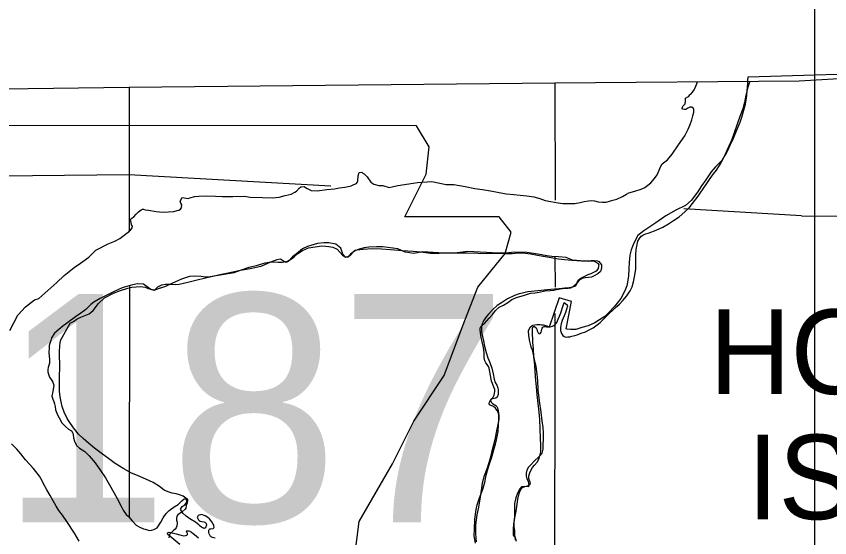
# Model space of a CAD drawing. Extents: x 77230 to 630905, y 790554 to 1662844.
# Drawn here: x 357646 to 367817, y 1633900 to 1640415 of the extents above; entities that cross this region are included whole.
import ezdxf

# ---------------------------------------------------------------- set-up
doc = ezdxf.new("R2010")
doc.units = 0
for name, color, linetype in [('Level 12', 7, 'Continuous'), ('Level 14', 7, 'Continuous'), ('Level 16', 7, 'Continuous'), ('Level 17', 7, 'Continuous'), ('Level 24', 7, 'Continuous'), ('Level 27', 7, 'Continuous'), ('Level 28', 7, 'Continuous')]:
    doc.layers.add(name, color=color, linetype=linetype)

msp = doc.modelspace()

# ---------------------------------------------------------------- linework, layer by layer
at = {"layer": 'Level 12'}
for points in [[(366796, 1639660), (368744, 1639716)], [(364322, 1636536), (364349, 1636542), (364368, 1636551), (364383, 1636563), (364393, 1636574), (364405, 1636591), (364422, 1636630), (364438, 1636668), (364454, 1636708), (364462, 1636734), (364475, 1636777), (364497, 1636841), (364534, 1636809), (364537, 1636790), (364536, 1636785), (364531, 1636768), (364522, 1636738), (364513, 1636712), (364498, 1636674), (364472, 1636613), (364460, 1636572), (364457, 1636557), (364453, 1636517), (364453, 1636491), (364463, 1636453), (364481, 1636425), (364498, 1636413), (364520, 1636406), (364542, 1636408), (364566, 1636412), (364594, 1636417), (364629, 1636427), (364659, 1636437), (364711, 1636456), (364763, 1636474), (364819, 1636501), (364861, 1636524), (364911, 1636559), (364949, 1636590), (364980, 1636621), (365017, 1636661), (365058, 1636700), (365104, 1636744), (365155, 1636791), (365189, 1636820), (365232, 1636865), (365280, 1636924), (365320, 1636983), (365347, 1637035), (365365, 1637098), (365381, 1637180), (365391, 1637259), (365393, 1637360), (365393, 1637430), (365398, 1637502), (365405, 1637544), (365420, 1637605), (365438, 1637639), (365459, 1637668), (365479, 1637681), (365507, 1637692), (365558, 1637709), (365648, 1637743), (365730, 1637781), (365802, 1637822), (365865, 1637863), (365934, 1637909), (366006, 1637970), (366059, 1638023), (366103, 1638075), (366172, 1638169), (366197, 1638205), (366281, 1638326), (366324, 1638388), (366365, 1638447), (366403, 1638494), (366439, 1638550), (366467, 1638601), (366499, 1638658), (366521, 1638696), (366543, 1638739), (366573, 1638805), (366613, 1638891), (366651, 1638982), (366697, 1639093), (366719, 1639154), (366763, 1639315), (366773, 1639368), (366779, 1639426), (366787, 1639491), (366789, 1639523), (366790, 1639535), (366793, 1639577), (366794, 1639611), (366796, 1639660)], [(359928, 1634063), (359886, 1634093), (359815, 1634136), (359772, 1634168), (359729, 1634206), (359701, 1634259), (359722, 1634289), (359733, 1634298), (359753, 1634312), (359769, 1634332), (359778, 1634352), (359776, 1634370), (359765, 1634394), (359734, 1634419), (359688, 1634438), (359645, 1634449), (359595, 1634458), (359543, 1634474), (359496, 1634496), (359437, 1634540), (359357, 1634590), (359264, 1634631), (359162, 1634677), (359087, 1634707), (358989, 1634761), (358883, 1634828), (358798, 1634890), (358723, 1634943), (358624, 1635018), (358550, 1635081), (358482, 1635141), (358424, 1635193), (358361, 1635274), (358308, 1635352), (358282, 1635391), (358245, 1635470), (358220, 1635541), (358206, 1635600), (358193, 1635661), (358188, 1635733), (358185, 1635811), (358185, 1635870), (358186, 1635935), (358191, 1636011), (358192, 1636090), (358188, 1636152), (358185, 1636222), (358189, 1636297), (358199, 1636363), (358321, 1636579), (358362, 1636601), (358409, 1636633), (358454, 1636655), (358557, 1636699), (358607, 1636739), (358673, 1636827), (358747, 1636897), (358863, 1636955), (358948, 1636990), (359039, 1637019), (359092, 1637030), (359147, 1637036), (359199, 1637040), (359258, 1637029), (359293, 1637012), (359368, 1636996), (359384, 1637001), (359398, 1637017), (359414, 1637035), (359465, 1637058), (359510, 1637066), (359561, 1637068), (359636, 1637064), (359682, 1637068), (359792, 1637092), (359893, 1637119), (360027, 1637153), (360122, 1637174), (360294, 1637202), (360372, 1637215), (360464, 1637247), (360557, 1637279), (360662, 1637307), (360758, 1637336), (360835, 1637346), (360921, 1637344), (360975, 1637341), (361039, 1637356), (361086, 1637383), (361125, 1637413), (361167, 1637451), (361223, 1637489), (361298, 1637523), (361465, 1637547), (361515, 1637543)], [(361515, 1637543), (361555, 1637539), (361606, 1637530), (361658, 1637506), (361723, 1637429), (361748, 1637413), (361780, 1637408)], [(361780, 1637408), (361802, 1637418), (361819, 1637434), (361837, 1637456), (361861, 1637477), (361885, 1637493), (361904, 1637499), (361978, 1637507), (362100, 1637513), (362212, 1637508), (362324, 1637500), (362477, 1637490), (362609, 1637479), (362700, 1637470), (362827, 1637457), (362934, 1637455), (363019, 1637458), (363105, 1637459), (363181, 1637459), (363283, 1637458), (363422, 1637455), (363530, 1637453), (363656, 1637455), (363761, 1637451), (363845, 1637451), (363922, 1637458), (363974, 1637458), (364074, 1637448), (364162, 1637431), (364209, 1637421), (364309, 1637405), (364426, 1637385), (364500, 1637377), (364591, 1637369), (364714, 1637360), (364791, 1637360), (364836, 1637362), (364878, 1637364), (364913, 1637360), (364929, 1637352), (364963, 1637311), (364965, 1637268), (364950, 1637226), (364916, 1637196), (364871, 1637171), (364838, 1637156), (364800, 1637151), (364759, 1637148), (364720, 1637138), (364679, 1637112), (364645, 1637068), (364612, 1637039), (364578, 1637020), (364545, 1637012), (364478, 1637010), (364436, 1637011), (364376, 1637007), (364283, 1636998), (364208, 1636990), (364041, 1636972), (363974, 1636955), (363935, 1636946), (363875, 1636925), (363790, 1636883), (363714, 1636836), (363658, 1636800), (363603, 1636753), (363551, 1636692), (363523, 1636658), (363490, 1636612), (363469, 1636559), (363464, 1636531), (363462, 1636502), (363463, 1636473), (363475, 1636416), (363487, 1636358), (363500, 1636292), (363520, 1636213), (363544, 1636147), (363566, 1636089), (363593, 1636018), (363607, 1635949), (363620, 1635882), (363635, 1635839), (363654, 1635805), (363667, 1635772), (363673, 1635746), (363670, 1635689), (363658, 1635656), (363642, 1635645), (363621, 1635639), (363601, 1635634), (363590, 1635632), (363576, 1635618), (363585, 1635593)], [(363890, 1633873), (363882, 1633906), (363875, 1633917), (363865, 1633931), (363862, 1633947), (363862, 1634006), (363868, 1634070), (363881, 1634147), (363895, 1634230), (363908, 1634318), (363917, 1634381), (363933, 1634454), (363945, 1634486), (363962, 1634515), (363977, 1634529), (364003, 1634540), (364024, 1634546), (364049, 1634554), (364055, 1634562), (364076, 1634578), (364073, 1634597), (364065, 1634617), (364059, 1634629), (364056, 1634639), (364056, 1634674), (364071, 1634725), (364102, 1634777), (364126, 1634808), (364158, 1634845), (364186, 1634891), (364207, 1634975), (364207, 1635058), (364201, 1635142), (364196, 1635261), (364191, 1635379), (364184, 1635470), (364173, 1635577), (364159, 1635687), (364149, 1635789), (364142, 1635865), (364133, 1635979), (364129, 1636058), (364119, 1636164), (364115, 1636256), (364105, 1636342), (364099, 1636481), (364102, 1636511), (364107, 1636531), (364112, 1636539), (364125, 1636539), (364145, 1636524), (364153, 1636507), (364159, 1636485), (364171, 1636461), (364181, 1636450), (364189, 1636448), (364196, 1636450), (364202, 1636456), (364208, 1636468), (364212, 1636485), (364216, 1636506), (364222, 1636520)], [(364222, 1636520), (364229, 1636530), (364245, 1636538), (364257, 1636538), (364277, 1636537), (364300, 1636535), (364322, 1636536)], [(363585, 1635593), (363596, 1635582), (363614, 1635570), (363631, 1635560), (363647, 1635548), (363654, 1635541), (363663, 1635523)], [(363663, 1635523), (363671, 1635485), (363678, 1635429), (363678, 1635382), (363672, 1635336), (363648, 1635213), (363629, 1635125), (363608, 1635042), (363590, 1634965), (363568, 1634877), (363533, 1634770), (363497, 1634673), (363473, 1634583), (363462, 1634518), (363438, 1634358), (363425, 1634280), (363406, 1634185), (363390, 1634063), (363388, 1633950), (363396, 1633850)], [(360134, 1633893), (360099, 1633903), (360084, 1633913), (360072, 1633924), (360058, 1633947), (360052, 1633965), (360053, 1633993), (360058, 1634003), (360066, 1634010), (360077, 1634013), (360108, 1634016), (360116, 1634024), (360121, 1634031), (360118, 1634047), (360115, 1634055), (360107, 1634071), (360092, 1634097), (360079, 1634116), (360061, 1634135), (360052, 1634143), (360008, 1634175), (359962, 1634191), (359922, 1634177), (359915, 1634170), (359909, 1634152), (359914, 1634140), (359925, 1634124), (359934, 1634116), (359947, 1634108), (359968, 1634104), (359989, 1634100), (360005, 1634093), (360013, 1634085), (360019, 1634077), (360023, 1634059), (360020, 1634045), (360018, 1634035), (360008, 1634024), (360003, 1634020), (359998, 1634017)], [(359998, 1634017), (359992, 1634018), (359981, 1634021), (359977, 1634023), (359962, 1634034), (359947, 1634046), (359928, 1634063)], [(359689, 1633815), (359541, 1633940), (359535, 1633957), (359537, 1633961), (359559, 1633968), (359593, 1633963), (359612, 1633957), (359645, 1633949), (359689, 1633936), (359723, 1633928), (359742, 1633924), (359768, 1633926), (359778, 1633931), (359787, 1633942), (359787, 1633944), (359787, 1633951), (359783, 1633960), (359775, 1633980), (359775, 1633982), (359779, 1633985), (359793, 1633988), (359802, 1633987), (359814, 1633982), (359822, 1633978), (359835, 1633970), (359857, 1633955), (359873, 1633940), (359899, 1633919), (359924, 1633897)]]:
    msp.add_lwpolyline(points, dxfattribs=at)
at = {"layer": 'Level 14'}
for points in [[(367437, 1639610), (369554, 1639734), (374777, 1639819), (378981, 1639866)], [(338556, 1639267), (343823, 1639351), (349273, 1639417), (354630, 1639473), (359059, 1639529), (364378, 1639584), (367437, 1639610)]]:
    msp.add_lwpolyline(points, dxfattribs=at)
at = {"layer": 'Level 16'}
for points in [[(359059, 1639529), (359058, 1638419), (359056, 1637728)], [(364378, 1639584), (364383, 1638118)], [(361579, 1638291), (359054, 1638435), (354628, 1638390)], [(367464, 1637920), (365992, 1638009)], [(367464, 1637920), (369592, 1637905), (374779, 1637490), (379177, 1637619)], [(364378, 1637415), (364384, 1637031)], [(359063, 1637037), (359057, 1634152)], [(364382, 1636702), (364374, 1632814), (364326, 1631279)]]:
    msp.add_lwpolyline(points, dxfattribs=at)
at = {"layer": 'Level 17'}
for points in [[(363575, 1638234), (363663, 1638219), (363773, 1638196), (363867, 1638189), (363947, 1638180), (364028, 1638170), (364116, 1638159), (364194, 1638138), (364260, 1638113), (364332, 1638099), (364422, 1638084), (364482, 1638077), (364566, 1638076), (364632, 1638076), (364698, 1638089), (364748, 1638099), (364802, 1638110), (364836, 1638114), (364876, 1638109), (364924, 1638097), (364972, 1638094), (365022, 1638094), (365106, 1638117), (365154, 1638132), (365227, 1638164), (365275, 1638193), (365305, 1638209), (365379, 1638230), (365459, 1638257), (365506, 1638277), (365580, 1638336), (365625, 1638389), (365659, 1638433), (365686, 1638491), (365702, 1638533), (365724, 1638570), (365787, 1638622), (365848, 1638693), (365927, 1638810), (366006, 1638921), (366047, 1639003), (366073, 1639064), (366092, 1639122), (366106, 1639172), (366117, 1639218), (366119, 1639250), (366115, 1639264), (366095, 1639280), (366069, 1639278), (366045, 1639266), (366019, 1639250), (366001, 1639249), (365981, 1639253), (365973, 1639257), (365973, 1639269), (365975, 1639279), (365984, 1639295), (366008, 1639323), (366016, 1639358), (366016, 1639392), (366045, 1639408), (366055, 1639416), (366073, 1639436), (366079, 1639442), (366103, 1639465), (366121, 1639495), (366124, 1639497), (366132, 1639513), (366144, 1639543), (366160, 1639585), (366162, 1639594)], [(366818, 1639600), (366810, 1639580), (366792, 1639530), (366767, 1639429), (366750, 1639339), (366729, 1639259), (366692, 1639164), (366659, 1639066), (366624, 1638957), (366592, 1638877), (366579, 1638845), (366532, 1638736), (366500, 1638670), (366467, 1638615), (366388, 1638534), (366336, 1638470), (366267, 1638371), (366216, 1638296), (366165, 1638218), (366084, 1638113), (366012, 1638052), (365893, 1637991), (365766, 1637923), (365641, 1637834), (365545, 1637767), (365494, 1637736), (365418, 1637678), (365369, 1637581), (365334, 1637497), (365317, 1637432), (365311, 1637338), (365306, 1637262), (365303, 1637168), (365280, 1637047), (365257, 1636983), (365204, 1636890), (365158, 1636830), (365121, 1636784), (365060, 1636717), (365004, 1636664), (364940, 1636624), (364879, 1636583), (364795, 1636546), (364717, 1636525), (364642, 1636500), (364576, 1636502), (364536, 1636507), (364520, 1636511), (364588, 1636852), (364436, 1636897), (364311, 1636531), (364283, 1636545), (364239, 1636554), (364213, 1636556), (364195, 1636558), (364181, 1636560), (364153, 1636558), (364129, 1636557), (364101, 1636551), (364091, 1636545), (364066, 1636523), (364048, 1636485), (364052, 1636422), (364063, 1636352), (364082, 1636287), (364096, 1636249), (364109, 1636191), (364121, 1636127), (364142, 1636041), (364157, 1635943), (364164, 1635859), (364167, 1635749), (364184, 1635609), (364204, 1635467), (364217, 1635361), (364232, 1635279), (364236, 1635211), (364235, 1635123), (364232, 1635059), (364228, 1635008), (364217, 1634958), (364177, 1634908), (364124, 1634859), (364078, 1634811), (364052, 1634780), (364031, 1634744), (364021, 1634708), (364021, 1634674), (364030, 1634638), (364046, 1634606), (364055, 1634552), (364049, 1634534), (364005, 1634540), (363963, 1634537), (363941, 1634509), (363914, 1634455), (363892, 1634398)], [(357565, 1636490), (357667, 1636681), (357760, 1636784), (357873, 1636872), (357929, 1636888), (358153, 1637089), (358244, 1637178), (358371, 1637277), (358450, 1637332), (358554, 1637405), (358641, 1637494), (358794, 1637572), (358880, 1637605), (358939, 1637639), (359033, 1637708), (359053, 1637720), (359062, 1637733), (359072, 1637741), (359094, 1637771), (359098, 1637791), (359086, 1637809), (359081, 1637839), (359073, 1637875), (359077, 1637883), (359115, 1637909), (359144, 1637944), (359174, 1637970), (359206, 1637996), (359226, 1638007), (359236, 1638007), (359256, 1637997), (359298, 1637993), (359394, 1637976), (359438, 1637973), (359496, 1637969), (359550, 1637972), (359616, 1637978), (359656, 1637989), (359680, 1637993), (359698, 1638007), (359715, 1638029), (359713, 1638039), (359715, 1638059), (359705, 1638081), (359697, 1638107), (359722, 1638150), (359796, 1638138), (359816, 1638145), (359880, 1638163), (359930, 1638168), (360030, 1638173), (360136, 1638166), (360226, 1638165), (360352, 1638164), (360494, 1638167), (360570, 1638156), (360726, 1638150), (360850, 1638147), (360934, 1638156), (361010, 1638176), (361084, 1638193), (361127, 1638216), (361151, 1638230), (361183, 1638268), (361205, 1638285), (361245, 1638289), (361275, 1638267), (361335, 1638238), (361407, 1638234), (361529, 1638250), (361625, 1638261), (361689, 1638271), (361755, 1638282), (361795, 1638288), (361833, 1638297), (361866, 1638313), (361902, 1638327), (361910, 1638340), (361918, 1638358), (361921, 1638422), (361933, 1638464), (361965, 1638468), (361979, 1638456), (361995, 1638447), (362035, 1638409), (362080, 1638343), (362116, 1638316), (362179, 1638302), (362225, 1638301), (362231, 1638301), (362309, 1638275), (362417, 1638299), (362556, 1638322), (362664, 1638339), (362842, 1638349), (363020, 1638315), (363116, 1638314), (363259, 1638287), (363381, 1638264), (363477, 1638249), (363575, 1638234)], [(361731, 1637441), (361704, 1637519), (361640, 1637568), (361556, 1637583), (361490, 1637584), (361412, 1637576), (361288, 1637540), (361226, 1637508), (361151, 1637447), (361099, 1637408), (361046, 1637350), (361022, 1637340), (360998, 1637345), (360948, 1637379), (360904, 1637374), (360826, 1637344), (360704, 1637290), (360571, 1637261), (360451, 1637238), (360297, 1637206), (360192, 1637183), (360140, 1637171), (360070, 1637160), (360006, 1637155), (359956, 1637163), (359892, 1637170), (359812, 1637163), (359712, 1637132), (359601, 1637081), (359511, 1637040), (359449, 1637020), (359447, 1637017), (359387, 1636997), (359370, 1636991), (359327, 1637000), (359299, 1637024), (359237, 1637067), (359159, 1637071), (359071, 1637052), (358971, 1637023), (358862, 1636974), (358770, 1636925), (358695, 1636890), (358617, 1636845), (358579, 1636813), (358542, 1636776), (358516, 1636752), (358454, 1636705), (358385, 1636658), (358292, 1636589), (358228, 1636543), (358176, 1636502), (358125, 1636454), (358085, 1636399), (358076, 1636363), (358056, 1636301), (358055, 1636275), (358053, 1636209), (358060, 1636133), (358060, 1636083), (358045, 1636026), (358041, 1636000), (358042, 1635972), (358048, 1635942), (358060, 1635906), (358091, 1635865), (358101, 1635845), (358115, 1635807), (358102, 1635727), (358092, 1635670), (358103, 1635630), (358117, 1635601), (358125, 1635573), (358130, 1635541), (358138, 1635499), (358161, 1635437), (358181, 1635397), (358216, 1635337), (358260, 1635288), (358298, 1635258), (358335, 1635234), (358353, 1635208), (358357, 1635188), (358361, 1635150), (358374, 1635108), (358400, 1635053), (358437, 1635019), (358505, 1634976), (358558, 1634924), (358634, 1634835), (358701, 1634739), (358762, 1634648), (358813, 1634562), (358864, 1634467), (358909, 1634391), (358956, 1634293), (358984, 1634245), (359021, 1634192), (359047, 1634164), (359093, 1634110), (359146, 1634059)], [(363568, 1635603), (363584, 1635633), (363590, 1635637), (363608, 1635657), (363618, 1635673), (363620, 1635683), (363629, 1635727), (363631, 1635753), (363617, 1635783), (363602, 1635825), (363588, 1635855), (363577, 1635927), (363569, 1635973), (363558, 1636017), (363550, 1636039), (363536, 1636063), (363518, 1636087), (363504, 1636109), (363497, 1636153), (363495, 1636213), (363488, 1636275), (363477, 1636331), (363467, 1636369), (363459, 1636401), (363450, 1636459), (363446, 1636497), (363448, 1636519), (363450, 1636527), (363463, 1636543), (363501, 1636575), (363560, 1636644), (363604, 1636692), (363639, 1636739), (363683, 1636779), (363739, 1636806), (363792, 1636840), (363844, 1636875), (363900, 1636902), (364000, 1636931), (364075, 1636955), (364133, 1636960), (364183, 1636968), (364257, 1636985), (364321, 1636990), (364367, 1636994), (364399, 1637003), (364431, 1637007), (364477, 1637019), (364505, 1637022), (364559, 1637026), (364599, 1637033), (364618, 1637037), (364644, 1637049), (364660, 1637081), (364660, 1637087), (364672, 1637117), (364692, 1637136), (364713, 1637148), (364745, 1637164), (364795, 1637187), (364835, 1637203), (364869, 1637218), (364893, 1637230), (364908, 1637242), (364928, 1637262), (364932, 1637292), (364934, 1637308), (364922, 1637326), (364869, 1637354), (364805, 1637353), (364649, 1637362), (364599, 1637369), (364521, 1637400), (364425, 1637409), (364343, 1637415), (364279, 1637424), (364167, 1637443), (364028, 1637462), (363876, 1637466), (363763, 1637455), (363669, 1637456), (363524, 1637463), (363290, 1637478), (363157, 1637461), (363047, 1637456), (362993, 1637455), (362728, 1637473), (362619, 1637452), (362509, 1637468), (362416, 1637508), (362230, 1637536), (362152, 1637533), (362056, 1637530), (361996, 1637521), (361932, 1637507), (361884, 1637484), (361857, 1637468), (361823, 1637432), (361797, 1637405), (361765, 1637403), (361731, 1637441)], [(363388, 1633833), (363371, 1633925), (363374, 1634009), (363381, 1634133), (363398, 1634251), (363409, 1634313), (363438, 1634400), (363475, 1634496), (363504, 1634591), (363523, 1634683), (363545, 1634771), (363566, 1634836), (363587, 1634896), (363603, 1634952), (363620, 1635014), (363638, 1635071), (363649, 1635125), (363670, 1635229), (363677, 1635311), (363681, 1635373), (363678, 1635430), (363670, 1635463), (363660, 1635491), (363637, 1635519), (363619, 1635537), (363605, 1635545), (363581, 1635551), (363565, 1635561), (363557, 1635574), (363563, 1635595), (363568, 1635603)], [(358434, 1633858), (358373, 1633959), (358276, 1634102), (358223, 1634180), (358180, 1634239), (358146, 1634295), (358109, 1634363), (358070, 1634429), (358028, 1634498), (357983, 1634582), (357971, 1634612), (357936, 1634670), (357892, 1634729), (357857, 1634771), (357760, 1634874), (357703, 1634948), (357653, 1635005), (357588, 1635073)], [(359146, 1634059), (359190, 1634033), (359236, 1634012), (359258, 1634006), (359284, 1633998), (359311, 1633992), (359335, 1633993), (359364, 1634001), (359408, 1634025), (359452, 1634094), (359483, 1634148), (359520, 1634203), (359558, 1634241), (359622, 1634288), (359671, 1634314), (359717, 1634359), (359747, 1634385), (359761, 1634391), (359775, 1634395), (359787, 1634380), (359787, 1634364), (359781, 1634337), (359772, 1634301), (359764, 1634269), (359756, 1634255), (359722, 1634225), (359696, 1634206), (359667, 1634186), (359653, 1634170), (359651, 1634142), (359651, 1634120), (359656, 1634096), (359656, 1634076), (359652, 1634048), (359644, 1634022), (359634, 1634008), (359611, 1633989), (359577, 1633959), (359563, 1633941), (359555, 1633897)], [(363892, 1634398), (363877, 1634326), (363876, 1634246), (363874, 1634164), (363869, 1634094), (363868, 1634040), (363874, 1633990), (363877, 1633928), (363881, 1633914), (363895, 1633856)]]:
    msp.add_lwpolyline(points, dxfattribs=at)
at = {"layer": 'Level 24'}
msp.add_lwpolyline([(355804, 1639050), (356146, 1636766), (355994, 1633302), (356299, 1633112), (356870, 1633112), (356870, 1631894), (361666, 1631894), (361894, 1632388), (361818, 1633188), (361932, 1634101), (362351, 1634825), (362617, 1635358), (362998, 1635929), (363226, 1636538), (363417, 1637032), (363759, 1637451), (363836, 1637718), (363683, 1637908), (362503, 1637908), (362770, 1638441), (362808, 1638783), (362650, 1639046)], close=True, dxfattribs=at)
at = {"layer": 'Level 28'}
msp.add_line((367630, 1481201), (367630, 1651480), dxfattribs=at)

# ---------------------------------------------------------------- texts
at = {"layer": 'Level 24'}
msp.add_text('187', height=2851.2, dxfattribs=at).set_placement((357436, 1634093))
at = {"layer": 'Level 27'}
for s, p in [('HOLIDAY', (366313, 1635696)), ('ISLAND', (366785, 1634131))]:
    msp.add_text(s, height=1056, dxfattribs=at).set_placement(p)

doc.saveas('drawing.dxf')
